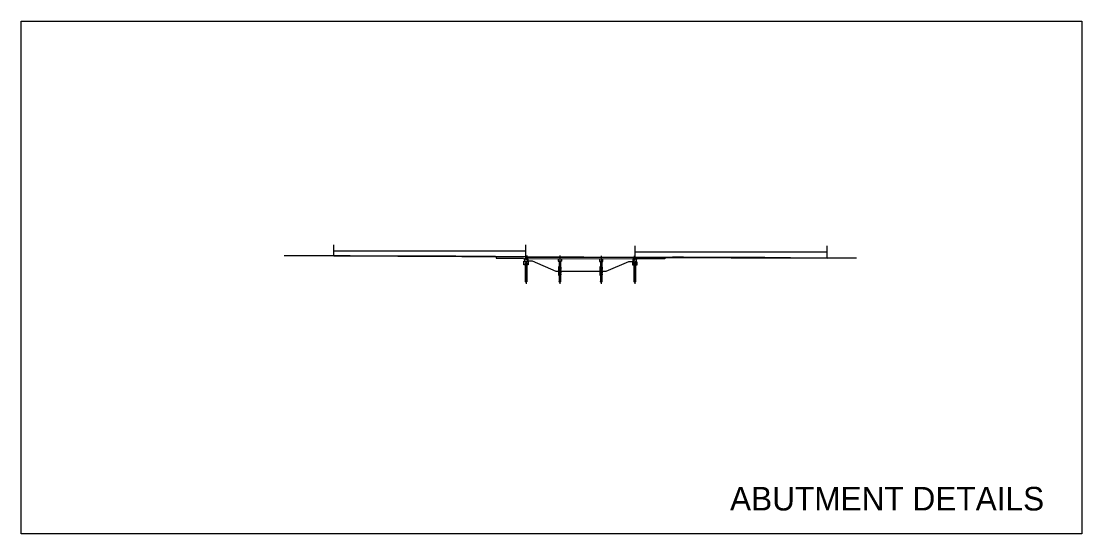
# Model space of a CAD drawing. Extents: x -2222 to 2066, y -217 to 964.
# Drawn here: x 1168 to 2066, y -217 to 217 of the extents above; entities that cross this region are included whole.
import ezdxf

# ---------------------------------------------------------------- set-up
doc = ezdxf.new("R2010")
doc.units = 0
for name, color, linetype in [('BR_P_Gen_Joint_Filler', 7, 'Continuous'), ('BR_P_Slab_Object', 7, 'Continuous'), ('BR_X_Gen_Approach_Slab', 7, 'Continuous'), ('BR_X_Slab_Object', 7, 'Continuous'), ('BR_X_Sub_Centerline', 7, 'Continuous'), ('BR_X_Sub_Deep_Centerline', 7, 'Continuous'), ('BR_X_Sub_Deep_Object', 7, 'Continuous'), ('BR_X_Sub_Object', 7, 'Continuous'), ('PF_X_Ground_Line', 7, 'Continuous'), ('SC_Scratch1', 7, 'Continuous'), ('XS_P_Pavt_Surface', 7, 'Continuous')]:
    doc.layers.add(name, color=color, linetype=linetype)

msp = doc.modelspace()

# ---------------------------------------------------------------- linework, layer by layer
at = {"layer": 'BR_P_Gen_Joint_Filler'}
for points in [[(1594.98, 17.41), (1595.02, 17.41), (1595.02, 17.24), (1594.98, 17.24)], [(1687.81, 16.98), (1687.76, 16.98), (1687.76, 16.81), (1687.81, 16.81)]]:
    msp.add_lwpolyline(points, close=True, dxfattribs=at)
at = {"layer": 'BR_P_Slab_Object'}
for p, q in [((1595.04, 17.43), (1595.02, 17.41)), ((1595.02, 17.41), (1595.02, 17.24)), ((1595.02, 17.24), (1687.76, 16.81)), ((1687.74, 17), (1595.04, 17.43)), ((1687.74, 17), (1687.76, 16.98)), ((1687.76, 16.81), (1687.76, 16.98))]:
    msp.add_line(p, q, dxfattribs=at)
at = {"layer": 'BR_X_Gen_Approach_Slab'}
for points in [[(1595.02, 17.32), (1570.02, 17.44), (1570.02, 16.36), (1593.21, 16.25), (1593.58, 15.88), (1594.16, 15.88)], [(1687.76, 16.9), (1712.76, 16.78), (1712.76, 15.7), (1689.55, 15.81), (1689.21, 15.47), (1688.63, 15.47)]]:
    msp.add_lwpolyline(points, dxfattribs=at)
at = {"layer": 'BR_X_Slab_Object'}
for p, q in [((1595.02, 17.41), (1687.76, 16.98)), ((1595.02, 16.08), (1595.02, 17.32)), ((1595.02, 17.32), (1687.76, 16.9)), ((1595.02, 17.3), (1687.76, 16.88)), ((1687.76, 16.9), (1687.76, 15.68))]:
    msp.add_line(p, q, dxfattribs=at)
at = {"layer": 'BR_X_Sub_Centerline'}
for p, q in [((1623.89, 18.63), (1623.89, -5.41)), ((1658.89, 18.47), (1658.89, -5.41)), ((1686.89, 18.34), (1686.89, 14.27)), ((1687.48, 14.03), (1687.48, -5.41))]:
    msp.add_line(p, q, dxfattribs=at)
at = {"layer": 'BR_X_Sub_Deep_Centerline'}
for p, q in [((1595.89, 18.75), (1595.89, 14.68)), ((1595.31, 13.51), (1595.31, -5.41))]:
    msp.add_line(p, q, dxfattribs=at)
at = {"layer": 'BR_X_Sub_Deep_Object'}
for p, q in [((1624.89, 9.06), (1622.89, 9.06)), ((1623.31, 13.69), (1623.31, -3.6)), ((1624.47, 13.69), (1624.47, -3.6)), ((1659.89, 9.06), (1657.89, 9.06)), ((1658.31, 13.53), (1658.31, -3.6)), ((1659.47, 13.53), (1659.47, -3.6))]:
    msp.add_line(p, q, dxfattribs=at)
for points in [[(1594.73, -3.6), (1594.73, 12.76), (1595.9, 12.76), (1595.9, -3.6)], [(1622.89, 9.06), (1622.71, 9.03), (1622.71, 8.97), (1622.89, 8.93), (1622.89, 8.87), (1622.71, 8.84), (1622.71, 8.77), (1622.89, 8.74), (1622.89, 8.68), (1622.71, 8.65), (1622.71, 8.58), (1622.89, 8.55), (1622.89, 8.48), (1622.71, 8.45), (1622.71, 8.39), (1622.89, 8.35), (1622.89, 8.29), (1622.71, 8.26), (1622.71, 8.19), (1622.89, 8.16), (1622.89, 8.1), (1622.71, 8.07), (1622.71, 8), (1622.89, 7.97), (1622.89, 7.91), (1622.71, 7.87), (1622.71, 7.81), (1622.89, 7.77), (1622.89, 7.71), (1622.71, 7.68), (1622.71, 7.61), (1622.89, 7.58), (1622.89, 7.52), (1622.71, 7.49), (1622.71, 7.42), (1622.89, 7.39), (1622.89, 7.33), (1622.71, 7.29), (1622.71, 7.23), (1622.89, 7.19), (1622.89, 7.13), (1622.71, 7.1), (1622.71, 7.03), (1622.89, 7), (1622.89, 6.94), (1622.71, 6.91), (1622.71, 6.84), (1622.89, 6.81), (1622.89, 6.75), (1622.71, 6.71), (1622.71, 6.65), (1622.89, 6.61), (1622.89, 6.55), (1622.71, 6.52), (1622.71, 6.45), (1622.89, 6.42), (1622.89, 6.36), (1622.71, 6.33), (1622.71, 6.26), (1622.89, 6.23), (1622.89, 6.17), (1622.71, 6.13), (1622.71, 6.07), (1622.89, 6.03), (1622.89, 5.97), (1622.71, 5.94), (1622.71, 5.87), (1622.89, 5.84), (1622.89, 5.78), (1622.71, 5.75), (1622.71, 5.68), (1622.89, 5.65), (1622.89, 5.59), (1622.71, 5.55), (1622.71, 5.49), (1622.89, 5.45), (1622.89, 5.39), (1622.71, 5.36), (1622.71, 5.29), (1622.89, 5.26), (1622.89, 5.2), (1622.71, 5.17), (1622.71, 5.1), (1622.89, 5.07), (1622.89, 5.01), (1622.71, 4.97), (1622.71, 4.91), (1622.89, 4.87), (1622.89, 4.81), (1622.71, 4.78), (1622.71, 4.71), (1622.89, 4.68), (1622.89, 4.62), (1622.71, 4.59), (1622.71, 4.52), (1622.89, 4.49), (1622.89, 4.43), (1622.71, 4.39), (1622.71, 4.33), (1622.89, 4.29), (1622.89, 4.23), (1622.71, 4.2), (1622.71, 4.13), (1622.89, 4.1), (1622.89, 4.04), (1622.71, 4.01), (1622.71, 3.94), (1622.89, 3.91), (1622.89, 3.85), (1622.71, 3.81), (1622.71, 3.75), (1622.89, 3.72), (1622.89, 3.65), (1622.71, 3.62), (1622.71, 3.55), (1622.89, 3.52), (1622.89, 3.46), (1622.71, 3.43), (1622.71, 3.36), (1622.89, 3.33), (1622.89, 3.27), (1622.71, 3.23), (1622.71, 3.17), (1622.89, 3.14), (1622.89, 3.07), (1622.71, 3.04), (1622.71, 2.97), (1622.89, 2.94), (1622.89, 2.88), (1622.71, 2.85), (1622.71, 2.78), (1622.89, 2.75), (1622.89, 2.69), (1622.71, 2.65), (1622.71, 2.59), (1622.89, 2.56), (1622.89, 2.49), (1622.71, 2.46), (1622.71, 2.39), (1622.89, 2.36), (1622.89, 2.3), (1622.71, 2.27), (1622.71, 2.2), (1622.89, 2.17), (1622.89, 2.11), (1622.71, 2.07), (1622.71, 2.06), (1625.07, 2.06), (1625.07, 2.07), (1624.89, 2.11), (1624.89, 2.17), (1625.07, 2.2), (1625.07, 2.27), (1624.89, 2.3), (1624.89, 2.36), (1625.07, 2.39), (1625.07, 2.46), (1624.89, 2.49), (1624.89, 2.56), (1625.07, 2.59), (1625.07, 2.65), (1624.89, 2.69), (1624.89, 2.75), (1625.07, 2.78), (1625.07, 2.85), (1624.89, 2.88), (1624.89, 2.94), (1625.07, 2.97), (1625.07, 3.04), (1624.89, 3.07), (1624.89, 3.14), (1625.07, 3.17), (1625.07, 3.23), (1624.89, 3.27), (1624.89, 3.33), (1625.07, 3.36), (1625.07, 3.43), (1624.89, 3.46), (1624.89, 3.52), (1625.07, 3.55), (1625.07, 3.62), (1624.89, 3.65), (1624.89, 3.72), (1625.07, 3.75), (1625.07, 3.81), (1624.89, 3.85), (1624.89, 3.91), (1625.07, 3.94), (1625.07, 4.01), (1624.89, 4.04), (1624.89, 4.1), (1625.07, 4.13), (1625.07, 4.2), (1624.89, 4.23), (1624.89, 4.29), (1625.07, 4.33), (1625.07, 4.39), (1624.89, 4.43), (1624.89, 4.49), (1625.07, 4.52), (1625.07, 4.59), (1624.89, 4.62), (1624.89, 4.68), (1625.07, 4.71), (1625.07, 4.78), (1624.89, 4.81), (1624.89, 4.87), (1625.07, 4.91), (1625.07, 4.97), (1624.89, 5.01), (1624.89, 5.07), (1625.07, 5.1), (1625.07, 5.17), (1624.89, 5.2), (1624.89, 5.26), (1625.07, 5.29), (1625.07, 5.36), (1624.89, 5.39), (1624.89, 5.45), (1625.07, 5.49), (1625.07, 5.55), (1624.89, 5.59), (1624.89, 5.65), (1625.07, 5.68), (1625.07, 5.75), (1624.89, 5.78), (1624.89, 5.84), (1625.07, 5.87), (1625.07, 5.94), (1624.89, 5.97), (1624.89, 6.03), (1625.07, 6.07), (1625.07, 6.13), (1624.89, 6.17), (1624.89, 6.23), (1625.07, 6.26), (1625.07, 6.33), (1624.89, 6.36), (1624.89, 6.42), (1625.07, 6.45), (1625.07, 6.52), (1624.89, 6.55), (1624.89, 6.61), (1625.07, 6.65), (1625.07, 6.71), (1624.89, 6.75), (1624.89, 6.81), (1625.07, 6.84), (1625.07, 6.91), (1624.89, 6.94), (1624.89, 7), (1625.07, 7.03), (1625.07, 7.1), (1624.89, 7.13), (1624.89, 7.19), (1625.07, 7.23), (1625.07, 7.29), (1624.89, 7.33), (1624.89, 7.39), (1625.07, 7.42), (1625.07, 7.49), (1624.89, 7.52), (1624.89, 7.58), (1625.07, 7.61), (1625.07, 7.68), (1624.89, 7.71), (1624.89, 7.77), (1625.07, 7.81), (1625.07, 7.87), (1624.89, 7.91), (1624.89, 7.97), (1625.07, 8), (1625.07, 8.07), (1624.89, 8.1), (1624.89, 8.16), (1625.07, 8.19), (1625.07, 8.26), (1624.89, 8.29), (1624.89, 8.35), (1625.07, 8.39), (1625.07, 8.45), (1624.89, 8.48), (1624.89, 8.55), (1625.07, 8.58), (1625.07, 8.65), (1624.89, 8.68), (1624.89, 8.74), (1625.07, 8.77), (1625.07, 8.84), (1624.89, 8.87), (1624.89, 8.93), (1625.07, 8.97), (1625.07, 9.03), (1624.89, 9.06)], [(1622.89, 9.06), (1623.31, 9.15), (1624.47, 9.15), (1624.89, 9.06)], [(1657.89, 9.06), (1657.71, 9.03), (1657.71, 8.97), (1657.89, 8.93), (1657.89, 8.87), (1657.71, 8.84), (1657.71, 8.77), (1657.89, 8.74), (1657.89, 8.68), (1657.71, 8.65), (1657.71, 8.58), (1657.89, 8.55), (1657.89, 8.48), (1657.71, 8.45), (1657.71, 8.39), (1657.89, 8.35), (1657.89, 8.29), (1657.71, 8.26), (1657.71, 8.19), (1657.89, 8.16), (1657.89, 8.1), (1657.71, 8.07), (1657.71, 8), (1657.89, 7.97), (1657.89, 7.91), (1657.71, 7.87), (1657.71, 7.81), (1657.89, 7.77), (1657.89, 7.71), (1657.71, 7.68), (1657.71, 7.61), (1657.89, 7.58), (1657.89, 7.52), (1657.71, 7.49), (1657.71, 7.42), (1657.89, 7.39), (1657.89, 7.33), (1657.71, 7.29), (1657.71, 7.23), (1657.89, 7.19), (1657.89, 7.13), (1657.71, 7.1), (1657.71, 7.03), (1657.89, 7), (1657.89, 6.94), (1657.71, 6.91), (1657.71, 6.84), (1657.89, 6.81), (1657.89, 6.75), (1657.71, 6.71), (1657.71, 6.65), (1657.89, 6.61), (1657.89, 6.55), (1657.71, 6.52), (1657.71, 6.45), (1657.89, 6.42), (1657.89, 6.36), (1657.71, 6.33), (1657.71, 6.26), (1657.89, 6.23), (1657.89, 6.17), (1657.71, 6.13), (1657.71, 6.07), (1657.89, 6.03), (1657.89, 5.97), (1657.71, 5.94), (1657.71, 5.87), (1657.89, 5.84), (1657.89, 5.78), (1657.71, 5.75), (1657.71, 5.68), (1657.89, 5.65), (1657.89, 5.59), (1657.71, 5.55), (1657.71, 5.49), (1657.89, 5.45), (1657.89, 5.39), (1657.71, 5.36), (1657.71, 5.29), (1657.89, 5.26), (1657.89, 5.2), (1657.71, 5.17), (1657.71, 5.1), (1657.89, 5.07), (1657.89, 5.01), (1657.71, 4.97), (1657.71, 4.91), (1657.89, 4.87), (1657.89, 4.81), (1657.71, 4.78), (1657.71, 4.71), (1657.89, 4.68), (1657.89, 4.62), (1657.71, 4.59), (1657.71, 4.52), (1657.89, 4.49), (1657.89, 4.43), (1657.71, 4.39), (1657.71, 4.33), (1657.89, 4.29), (1657.89, 4.23), (1657.71, 4.2), (1657.71, 4.13), (1657.89, 4.1), (1657.89, 4.04), (1657.71, 4.01), (1657.71, 3.94), (1657.89, 3.91), (1657.89, 3.85), (1657.71, 3.81), (1657.71, 3.75), (1657.89, 3.72), (1657.89, 3.65), (1657.71, 3.62), (1657.71, 3.55), (1657.89, 3.52), (1657.89, 3.46), (1657.71, 3.43), (1657.71, 3.36), (1657.89, 3.33), (1657.89, 3.27), (1657.71, 3.23), (1657.71, 3.17), (1657.89, 3.14), (1657.89, 3.07), (1657.71, 3.04), (1657.71, 2.97), (1657.89, 2.94), (1657.89, 2.88), (1657.71, 2.85), (1657.71, 2.78), (1657.89, 2.75), (1657.89, 2.69), (1657.71, 2.65), (1657.71, 2.59), (1657.89, 2.56), (1657.89, 2.49), (1657.71, 2.46), (1657.71, 2.39), (1657.89, 2.36), (1657.89, 2.3), (1657.71, 2.27), (1657.71, 2.2), (1657.89, 2.17), (1657.89, 2.11), (1657.71, 2.07), (1657.71, 2.06), (1660.07, 2.06), (1660.07, 2.07), (1659.89, 2.11), (1659.89, 2.17), (1660.07, 2.2), (1660.07, 2.27), (1659.89, 2.3), (1659.89, 2.36), (1660.07, 2.39), (1660.07, 2.46), (1659.89, 2.49), (1659.89, 2.56), (1660.07, 2.59), (1660.07, 2.65), (1659.89, 2.69), (1659.89, 2.75), (1660.07, 2.78), (1660.07, 2.85), (1659.89, 2.88), (1659.89, 2.94), (1660.07, 2.97), (1660.07, 3.04), (1659.89, 3.07), (1659.89, 3.14), (1660.07, 3.17), (1660.07, 3.23), (1659.89, 3.27), (1659.89, 3.33), (1660.07, 3.36), (1660.07, 3.43), (1659.89, 3.46), (1659.89, 3.52), (1660.07, 3.55), (1660.07, 3.62), (1659.89, 3.65), (1659.89, 3.72), (1660.07, 3.75), (1660.07, 3.81), (1659.89, 3.85), (1659.89, 3.91), (1660.07, 3.94), (1660.07, 4.01), (1659.89, 4.04), (1659.89, 4.1), (1660.07, 4.13), (1660.07, 4.2), (1659.89, 4.23), (1659.89, 4.29), (1660.07, 4.33), (1660.07, 4.39), (1659.89, 4.43), (1659.89, 4.49), (1660.07, 4.52), (1660.07, 4.59), (1659.89, 4.62), (1659.89, 4.68), (1660.07, 4.71), (1660.07, 4.78), (1659.89, 4.81), (1659.89, 4.87), (1660.07, 4.91), (1660.07, 4.97), (1659.89, 5.01), (1659.89, 5.07), (1660.07, 5.1), (1660.07, 5.17), (1659.89, 5.2), (1659.89, 5.26), (1660.07, 5.29), (1660.07, 5.36), (1659.89, 5.39), (1659.89, 5.45), (1660.07, 5.49), (1660.07, 5.55), (1659.89, 5.59), (1659.89, 5.65), (1660.07, 5.68), (1660.07, 5.75), (1659.89, 5.78), (1659.89, 5.84), (1660.07, 5.87), (1660.07, 5.94), (1659.89, 5.97), (1659.89, 6.03), (1660.07, 6.07), (1660.07, 6.13), (1659.89, 6.17), (1659.89, 6.23), (1660.07, 6.26), (1660.07, 6.33), (1659.89, 6.36), (1659.89, 6.42), (1660.07, 6.45), (1660.07, 6.52), (1659.89, 6.55), (1659.89, 6.61), (1660.07, 6.65), (1660.07, 6.71), (1659.89, 6.75), (1659.89, 6.81), (1660.07, 6.84), (1660.07, 6.91), (1659.89, 6.94), (1659.89, 7), (1660.07, 7.03), (1660.07, 7.1), (1659.89, 7.13), (1659.89, 7.19), (1660.07, 7.23), (1660.07, 7.29), (1659.89, 7.33), (1659.89, 7.39), (1660.07, 7.42), (1660.07, 7.49), (1659.89, 7.52), (1659.89, 7.58), (1660.07, 7.61), (1660.07, 7.68), (1659.89, 7.71), (1659.89, 7.77), (1660.07, 7.81), (1660.07, 7.87), (1659.89, 7.91), (1659.89, 7.97), (1660.07, 8), (1660.07, 8.07), (1659.89, 8.1), (1659.89, 8.16), (1660.07, 8.19), (1660.07, 8.26), (1659.89, 8.29), (1659.89, 8.35), (1660.07, 8.39), (1660.07, 8.45), (1659.89, 8.48), (1659.89, 8.55), (1660.07, 8.58), (1660.07, 8.65), (1659.89, 8.68), (1659.89, 8.74), (1660.07, 8.77), (1660.07, 8.84), (1659.89, 8.87), (1659.89, 8.93), (1660.07, 8.97), (1660.07, 9.03), (1659.89, 9.06)], [(1657.89, 9.06), (1658.31, 9.15), (1659.47, 9.15), (1659.89, 9.06)], [(1686.89, -3.6), (1686.89, 12.36), (1688.06, 12.36), (1688.06, -3.6)]]:
    msp.add_lwpolyline(points, dxfattribs=at)
for centre in [(1595.02, -3.6), (1623.6, -3.6), (1658.6, -3.6), (1687.18, -3.6)]:
    msp.add_circle(centre, 0.292, dxfattribs=at)
for centre in [(1595.6, -3.6), (1624.18, -3.6), (1659.18, -3.6), (1687.77, -3.6)]:
    msp.add_arc(centre, 0.292, 180, 0, dxfattribs=at)
at = {"layer": 'BR_X_Sub_Object'}
for p, q in [((1597.05, 16.09), (1685.74, 15.68)), ((1622.45, 15.97), (1622.45, 13.69)), ((1622.45, 13.69), (1625.34, 13.69)), ((1625.34, 15.95), (1625.34, 13.69)), ((1657.45, 15.81), (1657.45, 13.53)), ((1657.45, 13.53), (1660.34, 13.53)), ((1660.34, 13.53), (1660.34, 15.79)), ((1686.32, 13.36), (1686.32, 15.68)), ((1686.32, 15.68), (1687.04, 15.68)), ((1687.04, 15.68), (1687.04, 15.47)), ((1687.04, 15.47), (1687.76, 15.47)), ((1687.76, 15.47), (1687.76, 15.68)), ((1687.76, 15.68), (1688.63, 15.68)), ((1688.63, 15.68), (1688.63, 13.36))]:
    msp.add_line(p, q, dxfattribs=at)
for points in [[(1593.58, 13.76), (1597.04, 13.76), (1597.04, 10.76), (1593.58, 10.76)], [(1685.74, 13.36), (1689.21, 13.36), (1689.21, 10.36), (1685.74, 10.36)]]:
    msp.add_lwpolyline(points, close=True, dxfattribs=at)
for points in [[(1594.16, 13.76), (1594.16, 16.08), (1595.02, 16.08), (1595.02, 15.88), (1595.75, 15.88), (1595.75, 16.08), (1596.47, 16.08), (1596.47, 13.76)], [(1597.04, 13.76), (1597.04, 16.08), (1596.47, 16.08)], [(1686.32, 15.68), (1685.74, 15.68), (1685.74, 13.36)]]:
    msp.add_lwpolyline(points, dxfattribs=at)
at = {"layer": 'PF_X_Ground_Line'}
msp.add_line((1569.39, 17.82), (1719.39, 17.13), dxfattribs=at)
msp.add_lwpolyline([(1685.74, 13.36), (1682.13, 13.36), (1662.76, 5.06), (1620.96, 5.06), (1600.65, 13.76), (1597.04, 13.76)], dxfattribs=at)
for centre, radius, start, end in [((1360.3, -45436.86), 45455.15, 89.736441, 89.962063), ((-974959.95, -221977800.09), 221979965.85, 89.74789324, 89.7479061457), ((-4859047.62, -1350237348.2), 1350246114.48, 89.79373555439, 89.79373767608), ((2031.9, 62517.39), 62501.03, 269.8051954, 269.8564126)]:
    msp.add_arc(centre, radius, start, end, dxfattribs=at)
at = {"layer": 'SC_Scratch1'}
for p, q in [((1432.52, 18.24), (1432.52, 27.6)), ((1595.02, 17.41), (1595.02, 27.6)), ((1432.52, 22.65), (1595.02, 22.65)), ((1687.76, 16.83), (1687.76, 26.74)), ((1687.76, 21.79), (1850.26, 21.79)), ((1850.26, 16.63), (1850.26, 26.74)), ((1595.02, 17.24), (1687.76, 16.81)), ((1596.44, 17.32), (1596.44, 17.61))]:
    msp.add_line(p, q, dxfattribs=at)
msp.add_lwpolyline([(1167.85, 217.02), (2065.9, 217.02), (2065.9, -217.02), (1167.85, -217.02)], close=True, dxfattribs=at)
for points in [[(1594.16, 15.81), (1595.02, 15.81), (1595.02, 15.61), (1595.75, 15.61), (1595.75, 15.81), (1596.47, 15.81)], [(1688.63, 15.41), (1687.76, 15.41), (1687.76, 15.2), (1687.04, 15.2), (1687.04, 15.41), (1686.32, 15.41)]]:
    msp.add_lwpolyline(points, dxfattribs=at)
at = {"layer": 'XS_P_Pavt_Surface'}
for p, q in [((1594.96, 17.43), (1432.52, 18.24)), ((1432.52, 18.24), (1432.52, 18.11)), ((1595.02, 17.3), (1432.52, 18.11)), ((1594.96, 17.43), (1594.98, 17.41)), ((1687.76, 16.88), (1850.26, 16.5)), ((1687.83, 17), (1687.81, 16.98)), ((1687.83, 17), (1850.26, 16.63)), ((1850.26, 16.5), (1850.26, 16.63))]:
    msp.add_line(p, q, dxfattribs=at)

# ---------------------------------------------------------------- texts
at = {"layer": 'SC_Scratch1'}
msp.add_text('ABUTMENT DETAILS', height=20, dxfattribs=at).set_placement((1768.04, -197.3))

doc.saveas('drawing.dxf')
